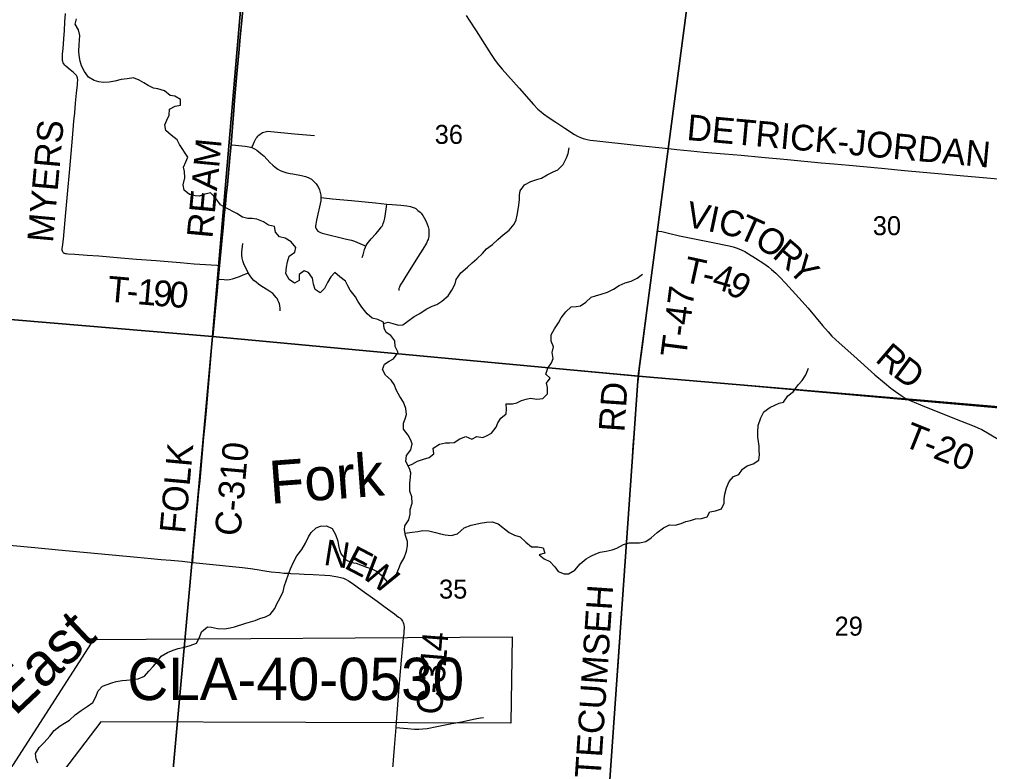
# Model space of a CAD drawing. Extents: x 0 to 1134, y 0 to 440.
# Drawn here: x 363.6 to 427.8, y 252.5 to 301.5 of the extents above; entities that cross this region are included whole.
import ezdxf

# ---------------------------------------------------------------- set-up
doc = ezdxf.new("R2010")
doc.units = 0
for name, color, linetype in [('GM_X_County_Road', 7, 'Continuous'), ('GM_X_County_Road_Text', 7, 'Continuous'), ('GM_X_Minor_River', 7, 'Continuous'), ('GM_X_Minor_River_Text', 7, 'Continuous'), ('GM_X_Section', 7, 'Continuous'), ('GM_X_Section_Text', 7, 'Continuous'), ('GM_X_Township', 7, 'Continuous'), ('GM_X_Township_Road', 7, 'Continuous'), ('GM_X_Township_Road_Text', 7, 'Continuous'), ('GM_X_Unincorporated', 7, 'Continuous'), ('SH_Text', 7, 'Continuous')]:
    doc.layers.add(name, color=color, linetype=linetype)

msp = doc.modelspace()

# ---------------------------------------------------------------- linework, layer by layer
at = {"layer": 'GM_X_County_Road'}
for points in [[(377.656, 293.203), (377.748, 294.36), (377.835, 295.474), (377.89, 296.123), (378.043, 297.887), (378.167, 299.278), (378.26, 300.299), (378.36, 301.413), (378.469, 302.619), (378.568, 303.733), (378.631, 304.475), (378.722, 305.496), (378.796, 306.331), (378.866, 307.167), (378.963, 308.187), (379.042, 309.021), (379.106, 309.67), (379.185, 310.598), (379.201, 310.758)], [(393.199, 301.754), (393.409, 301.448), (393.858, 300.74), (394.86, 299.168), (395.122, 298.781), (395.348, 298.483), (395.587, 298.196), (396.7, 296.94), (397.661, 295.866), (397.95, 295.567), (398.166, 295.372), (398.311, 295.254), (398.691, 294.983), (399.126, 294.698), (399.725, 294.299), (400.359, 293.89), (400.559, 293.778), (400.755, 293.69), (400.947, 293.618), (401.204, 293.557), (401.409, 293.517), (401.845, 293.459), (404.441, 293.182), (406.575, 292.952)], [(377.072, 287.079), (377.134, 287.694), (377.21, 288.526), (377.282, 289.267), (377.337, 289.823), (377.411, 290.564), (377.586, 292.321), (377.623, 292.783), (377.656, 293.203)], [(406.575, 292.952), (407.128, 292.893), (408.056, 292.804), (408.89, 292.724), (410.284, 292.606), (411.397, 292.511), (412.736, 292.379), (414.46, 292.227), (416.686, 292.018), (417.522, 291.947), (418.542, 291.853), (420.676, 291.65), (422.19, 291.51), (424.667, 291.287), (425.874, 291.177), (427.638, 291.021), (429.308, 290.872), (430.33, 290.787), (432, 290.631), (434.042, 290.447), (435.244, 290.336), (436.24, 290.246)], [(376.893, 285.198), (377.023, 286.581), (377.072, 287.079)], [(376.811, 284.307), (376.848, 284.726), (376.893, 285.198)], [(376.448, 280.503), (376.653, 282.628), (376.741, 283.52), (376.811, 284.307)], [(375.112, 265.584), (375.144, 266.058), (375.336, 268.189), (375.528, 270.228), (375.595, 270.97), (375.688, 271.989), (375.855, 273.844), (375.93, 274.678), (376.016, 275.605), (376.154, 277.181), (376.407, 280.056), (376.448, 280.503)], [(349.613, 267.99), (350.203, 267.933), (351.131, 267.845), (352.616, 267.712), (353.822, 267.601), (354.473, 267.548), (355.029, 267.505), (356.974, 267.342), (357.437, 267.3), (357.992, 267.241), (358.825, 267.144), (359.845, 267.04), (360.864, 266.934), (361.605, 266.857), (362.997, 266.723), (364.667, 266.562), (366.244, 266.414), (371.44, 265.931), (372.368, 265.844), (373.017, 265.783), (373.666, 265.723), (374.417, 265.654), (375.112, 265.584)], [(375.112, 265.584), (376.67, 265.424), (377.745, 265.319), (378.409, 265.244), (378.937, 265.169), (379.372, 265.101), (379.881, 265.014), (380.3, 264.958), (380.847, 264.902), (381.133, 264.878), (381.422, 264.859), (381.613, 264.85), (382.159, 264.825), (382.49, 264.809), (383.071, 264.781), (383.862, 264.732), (384.195, 264.704), (384.44, 264.675), (384.717, 264.632), (384.901, 264.589), (385.08, 264.531), (385.253, 264.455), (385.418, 264.364), (385.653, 264.209), (386.33, 263.72), (386.63, 263.502), (386.858, 263.339), (387.31, 263.007), (387.662, 262.75), (387.99, 262.512), (388.46, 262.169), (388.733, 261.968), (388.812, 261.907), (388.895, 261.827), (388.945, 261.759), (388.993, 261.688), (389.032, 261.614), (389.06, 261.534), (389.078, 261.439), (389.088, 261.333), (389.09, 261.214), (389.079, 261.049), (389.067, 260.883), (389.041, 260.586), (388.844, 258.357), (388.749, 257.337), (388.565, 255.016), (388.54, 254.662)], [(388.54, 254.662), (388.432, 253.348), (388.25, 251.119), (388.228, 250.748), (388.223, 250.621), (388.229, 250.471), (388.245, 250.287), (388.277, 250.107), (388.302, 250.019), (388.333, 249.934), (388.37, 249.851), (388.414, 249.772), (388.464, 249.696), (388.52, 249.623), (388.566, 249.571)]]:
    msp.add_lwpolyline(points, dxfattribs=at)
at = {"layer": 'GM_X_Minor_River'}
for points in [[(381.224, 287.015), (380.861, 287.122), (380.591, 287.433), (380.527, 287.787), (380.13, 287.883), (379.802, 288.104), (379.36, 288.291), (379.041, 288.329), (378.757, 288.333), (378.404, 288.417), (378.031, 288.661), (377.261, 289.057), (376.956, 289.22), (376.665, 289.623), (376.282, 290.015), (375.859, 289.906), (375.55, 289.796), (375.265, 289.822), (374.891, 289.918), (374.552, 290.195), (374.477, 290.561), (374.597, 291.015), (374.579, 291.437), (374.503, 291.723), (374.655, 292.075), (374.796, 292.392), (374.237, 293.219), (374.081, 293.529), (373.697, 293.841), (373.337, 294.142), (373.273, 294.519), (373.402, 294.825), (373.554, 295.165), (373.582, 295.552), (373.949, 295.753), (374.303, 295.828), (374.297, 296.193), (373.923, 296.425), (373.616, 296.452), (373.244, 296.764), (372.801, 296.895), (372.517, 296.955), (372.166, 297.119), (371.872, 297.293), (371.566, 297.468), (371.192, 297.632), (370.77, 297.557), (370.37, 297.517), (369.97, 297.419), (369.582, 297.344), (369.183, 297.326), (368.898, 297.363), (368.603, 297.458), (368.23, 297.679), (367.95, 298.047), (367.76, 298.414), (367.673, 298.723), (367.609, 299.1), (367.59, 299.385), (367.596, 299.818), (367.634, 300.125), (367.649, 300.433), (367.562, 300.81), (367.339, 301.177), (367.423, 301.529)], [(387.739, 281.378), (388.049, 281.474), (388.356, 281.38), (388.73, 281.273), (389.016, 281.303), (389.349, 281.527), (389.763, 281.853), (390.13, 282.042), (390.556, 282.334), (390.957, 282.534), (391.255, 282.645), (391.588, 282.869), (392.014, 283.206), (392.258, 283.59), (392.468, 283.998), (392.529, 284.282), (392.842, 284.723), (393.28, 285.117), (393.591, 285.398), (393.902, 285.668), (394.271, 286.017), (394.549, 286.31), (394.94, 286.602), (395.286, 286.929), (395.654, 287.255), (396.045, 287.547), (396.381, 287.941), (396.498, 288.236), (396.582, 288.555), (396.632, 288.919), (396.693, 289.203), (396.72, 289.579), (396.724, 289.864), (396.773, 290.159), (397.063, 290.543), (397.476, 290.767), (397.865, 290.899), (398.185, 290.998), (398.564, 291.221), (398.954, 291.41), (399.252, 291.543), (399.621, 291.892), (399.843, 292.334), (399.938, 292.629), (400.022, 292.993)], [(382.777, 267.264), (382.94, 267.558), (383.274, 267.862), (383.572, 267.984), (383.971, 267.99), (384.333, 267.826), (384.556, 267.425), (384.722, 266.99), (384.764, 266.704), (384.828, 266.407), (384.927, 266.12), (385.23, 265.741), (385.615, 265.565), (385.923, 265.539), (386.32, 265.374), (386.615, 265.268), (386.91, 265.173), (387.272, 265.009), (387.644, 264.697), (387.947, 264.317), (388.325, 264.427), (388.58, 264.766), (388.744, 265.174), (388.851, 265.469), (389.095, 265.888), (389.26, 266.331), (389.322, 266.672), (389.325, 266.969), (389.193, 267.358), (389.118, 267.724), (389.145, 268.009), (389.4, 268.405), (389.485, 268.78), (389.489, 269.076), (389.62, 269.508), (389.613, 269.907), (389.47, 270.296), (389.477, 270.821), (389.516, 271.219), (389.542, 271.504), (389.443, 271.802), (389.21, 272.249), (389.249, 272.659), (389.55, 273.032), (389.623, 273.43), (389.524, 273.716), (389.357, 274.003), (389.054, 274.394), (389.059, 274.782), (389.165, 275.077), (389.26, 275.372), (389.219, 275.749), (389.065, 276.173), (388.819, 276.552), (388.597, 276.954), (388.442, 277.343), (388.24, 277.642), (387.857, 277.954), (387.657, 278.344), (387.809, 278.684), (388.097, 278.898), (388.384, 279.054), (388.708, 279.46), (388.507, 279.85), (388.478, 280.227), (388.209, 280.583), (387.915, 280.781), (387.771, 281.067), (387.73, 281.467), (387.368, 281.653), (386.981, 281.726), (386.655, 282.027), (386.307, 282.453), (386.027, 282.855), (385.882, 283.142), (385.534, 283.579), (385.379, 283.877), (385.223, 284.187), (384.839, 284.476), (384.512, 284.765), (384.247, 284.472), (384.025, 284.098), (383.826, 283.69), (383.538, 283.409), (383.222, 283.64), (383.112, 283.984), (383.037, 284.384), (382.78, 284.751), (382.485, 284.857), (382.163, 284.622), (382.147, 284.235), (381.837, 284.056), (381.487, 284.299), (381.264, 284.69), (381.326, 285.111), (381.376, 285.452), (381.495, 285.838), (381.862, 286.096), (381.935, 286.403), (381.62, 286.783), (381.224, 287.015)], [(389.356, 271.968), (389.618, 272.085), (389.985, 272.274), (390.374, 272.418), (390.763, 272.516), (391.051, 272.763), (391.01, 273.129), (391.435, 273.408), (391.823, 273.495), (392.108, 273.48), (392.405, 273.5), (392.784, 273.746), (393.173, 273.901), (393.581, 273.725), (393.903, 273.904), (394.301, 273.842), (394.587, 273.975), (394.885, 274.12), (395.175, 274.527), (395.305, 274.822), (395.491, 275.128), (395.847, 275.397), (395.874, 275.705), (395.856, 276.07), (396.266, 276.076), (396.552, 276.141), (396.85, 276.297), (397.17, 276.373), (397.456, 276.45), (397.877, 276.376), (398.265, 276.417), (398.576, 276.733), (398.582, 277.143), (398.517, 277.429), (398.76, 277.768), (398.467, 278.034), (398.609, 278.431), (398.853, 278.782), (398.959, 279.077), (398.895, 279.454), (398.969, 279.829), (398.825, 280.219), (398.831, 280.64), (399.041, 281.025), (399.296, 281.421), (399.483, 281.761), (399.796, 282.156), (400.153, 282.494), (400.472, 282.513), (400.758, 282.555), (401.114, 282.802), (401.46, 283.117), (401.746, 283.205), (402.124, 283.326), (402.547, 283.458), (402.937, 283.658), (403.316, 283.905), (403.717, 284.06), (404.117, 284.192), (404.507, 284.381), (404.864, 284.639)], [(389.163, 267.505), (389.618, 267.581), (389.995, 267.634), (390.337, 267.687), (390.724, 267.67), (391.179, 267.551), (391.497, 267.479), (391.815, 267.395), (392.202, 267.357), (392.625, 267.477), (393.074, 267.871), (393.533, 268.048), (393.841, 268.101), (394.127, 268.166), (394.538, 268.241), (394.914, 268.259), (395.311, 268.141), (396.045, 267.562), (396.407, 267.386), (396.77, 267.268), (397.142, 266.922), (397.526, 266.621), (397.936, 266.616), (398.3, 266.543), (398.398, 266.2), (398.032, 266.079), (398.348, 265.813), (398.744, 265.637), (399.059, 265.28), (399.294, 264.98), (399.68, 264.828), (399.976, 264.824), (400.378, 265.059), (400.748, 265.488), (401.139, 265.814), (401.45, 266.004), (401.77, 266.148), (402.068, 266.259), (402.468, 266.323), (402.856, 266.409), (403.165, 266.52), (403.602, 266.765), (403.979, 266.875), (404.264, 266.883), (404.663, 266.867), (405.074, 266.965), (405.43, 267.211), (405.834, 267.548), (406.248, 267.874), (406.638, 268.064), (407.013, 268.036), (407.414, 268.157), (407.734, 268.279), (408.032, 268.344), (408.363, 268.454), (408.763, 268.495), (409.129, 268.593), (409.315, 268.933), (409.692, 268.985), (410.081, 269.129), (410.268, 269.492), (410.261, 269.788), (410.299, 270.084), (410.429, 270.516), (410.594, 270.936), (410.883, 271.252), (411.227, 271.385), (411.482, 271.758), (411.781, 271.971), (412.193, 272.103), (412.561, 272.338), (412.599, 272.703), (412.58, 272.988), (412.572, 273.273), (412.542, 273.57), (412.489, 273.856), (412.482, 274.209), (412.521, 274.642), (412.687, 275.153), (412.897, 275.538), (413.277, 275.819), (413.609, 275.986), (413.896, 276.108), (414.182, 276.185), (414.483, 276.603), (414.852, 276.884), (415.153, 277.325), (415.419, 277.618), (415.663, 277.992), (415.84, 278.434)], [(364.868, 252.292), (364.757, 252.589), (364.705, 252.944), (364.949, 253.34), (365.295, 253.666), (365.665, 254.084), (365.943, 254.456), (366.335, 254.782), (366.633, 254.938), (366.955, 255.151), (367.335, 255.5), (367.726, 255.792), (368.129, 256.06), (368.496, 256.307), (368.706, 256.692), (368.859, 257.078), (369.137, 257.405), (369.446, 257.504), (369.755, 257.626), (370.041, 257.702), (370.441, 257.766), (370.737, 257.796), (371.148, 257.826), (371.502, 257.89), (371.915, 258.067), (372.215, 258.383), (372.504, 258.699), (372.735, 258.992), (373.036, 259.376), (373.438, 259.622), (373.828, 259.777), (374.159, 259.876), (374.56, 259.985), (374.949, 260.094), (375.361, 260.249), (375.57, 260.611), (375.7, 260.986), (376.081, 261.312), (376.365, 261.297), (376.763, 261.201), (377.207, 261.196), (377.596, 261.26), (377.881, 261.325), (378.636, 261.567), (378.945, 261.654), (379.243, 261.73), (379.552, 261.864), (379.929, 261.984), (380.228, 262.14), (380.54, 262.536), (380.681, 262.842), (380.902, 263.238), (381.09, 263.647), (381.186, 264.044), (381.293, 264.351), (381.458, 264.794), (381.588, 265.157), (381.787, 265.599), (381.997, 266.019), (382.333, 266.436), (382.578, 266.855), (382.777, 267.264)]]:
    msp.add_lwpolyline(points, dxfattribs=at)
at = {"layer": 'GM_X_Section'}
for points in [[(349.223, 313.27), (378.992, 310.617), (376.424, 280.529), (346.29, 283.052)], [(378.992, 310.617), (408.53, 307.786), (404.58, 277.901), (376.424, 280.529)], [(408.53, 307.786), (437.721, 305.198), (434.906, 275.318), (404.58, 277.901)], [(346.29, 283.052), (376.424, 280.529), (373.702, 250.716), (343.437, 253.571)], [(376.424, 280.529), (404.58, 277.901), (402.471, 248.078), (373.702, 250.716)], [(404.58, 277.901), (434.906, 275.318), (432.306, 245.32), (402.471, 248.078)]]:
    msp.add_lwpolyline(points, close=True, dxfattribs=at)
at = {"layer": 'GM_X_Township'}
msp.add_lwpolyline([(300.527, 287.945), (340.569, 283.778), (346.334, 283.109), (376.441, 280.519), (404.61, 277.916), (422.488, 276.334), (434.927, 275.233)], dxfattribs=at)
at = {"layer": 'GM_X_Township_Road'}
for points in [[(376.893, 285.198), (376.703, 285.211), (375.201, 285.314), (374.273, 285.394), (372.696, 285.522), (371.398, 285.625), (370.362, 285.71), (368.897, 285.825), (368.131, 285.884), (367.312, 285.948), (366.848, 285.974), (366.753, 285.98), (366.705, 285.988), (366.657, 286.002), (366.616, 286.021), (366.572, 286.052), (366.541, 286.085), (366.512, 286.13), (366.494, 286.174), (366.484, 286.225), (366.48, 286.272), (366.48, 286.337), (366.491, 286.446), (366.564, 286.969), (366.729, 288.73), (366.83, 289.936), (366.977, 291.606), (367.167, 293.646), (367.26, 294.759), (367.306, 295.316), (367.364, 295.964), (367.429, 296.612), (367.49, 297.167), (367.501, 297.314), (367.504, 297.444), (367.507, 297.515), (367.5, 297.57), (367.488, 297.632), (367.464, 297.699), (367.416, 297.781), (367.369, 297.84), (367.313, 297.899), (367.222, 297.984), (367.013, 298.169), (366.729, 298.412), (366.661, 298.478), (366.598, 298.55), (366.548, 298.63), (366.529, 298.673), (366.515, 298.719), (366.505, 298.767), (366.499, 298.813), (366.497, 298.908), (366.51, 299.189), (366.535, 299.56), (366.582, 300.209), (366.622, 300.766), (366.658, 301.324), (366.705, 301.881)], [(379.031, 293.011), (379.05, 293.063), (379.124, 293.272), (379.189, 293.424), (379.261, 293.554), (379.312, 293.632), (379.368, 293.707), (379.429, 293.777), (379.496, 293.842), (379.567, 293.903), (379.644, 293.957), (379.724, 294.003), (379.81, 294.04), (379.899, 294.068), (379.99, 294.087), (380.083, 294.094), (380.27, 294.086), (381.85, 293.934), (383.168, 293.82)], [(377.656, 293.203), (377.719, 293.198), (377.937, 293.181), (378.585, 293.111), (378.841, 293.068), (379.031, 293.011)], [(379.031, 293.011), (379.193, 292.942), (379.354, 292.842), (379.483, 292.745), (379.628, 292.633), (379.832, 292.444), (380.22, 292.04), (380.423, 291.844), (380.568, 291.724), (380.733, 291.598), (380.898, 291.507), (381.08, 291.437), (381.333, 291.355), (381.56, 291.306), (381.737, 291.276), (382.311, 291.163), (382.563, 291.107), (382.741, 291.046), (382.885, 290.981), (382.976, 290.924), (383.046, 290.868), (383.156, 290.753), (383.219, 290.687), (383.277, 290.617), (383.33, 290.543), (383.422, 290.384), (383.494, 290.215), (383.548, 290.04), (383.581, 289.86), (383.59, 289.769), (383.591, 289.725)], [(405.863, 287.511), (405.99, 288.498), (406.266, 290.617), (406.462, 292.091), (406.533, 292.636), (406.566, 292.887), (406.575, 292.952)], [(383.591, 289.725), (383.592, 289.677), (383.588, 289.586), (383.577, 289.495), (383.308, 288.219), (383.253, 287.943), (383.242, 287.847), (383.244, 287.747), (383.268, 287.652), (383.32, 287.567), (383.39, 287.494), (383.472, 287.435), (383.572, 287.393), (383.676, 287.363), (385.289, 286.968), (385.616, 286.889), (385.824, 286.819), (386.17, 286.676), (386.421, 286.557), (386.563, 286.49)], [(383.591, 289.725), (383.775, 289.702), (384.329, 289.635), (385.625, 289.508), (387.199, 289.359), (387.948, 289.284)], [(386.563, 286.49), (386.585, 286.541), (386.659, 286.658), (386.732, 286.766), (386.906, 286.98), (387.218, 287.322), (387.471, 287.596), (387.585, 287.746), (387.636, 287.826), (387.681, 287.909), (387.72, 287.995), (387.782, 288.173), (387.827, 288.355), (387.874, 288.631), (387.927, 289.092), (387.948, 289.284)], [(387.948, 289.284), (388.31, 289.248), (388.881, 289.202), (389.268, 289.159), (389.512, 289.111), (389.69, 289.063), (389.781, 289.028), (389.864, 288.981), (389.947, 288.924), (390.012, 288.866), (390.152, 288.744), (390.217, 288.677), (390.277, 288.606), (390.332, 288.531), (390.428, 288.372), (390.551, 288.122), (390.624, 287.95), (390.683, 287.774), (390.722, 287.592), (390.74, 287.407), (390.74, 287.314), (390.735, 287.221), (390.724, 287.129), (390.706, 287.038), (390.681, 286.948), (390.649, 286.861), (390.571, 286.692), (390.336, 286.291), (389.991, 285.739), (389.143, 284.404), (389.003, 284.18), (388.838, 283.91), (388.781, 283.78), (388.751, 283.688), (388.739, 283.569)], [(404.617, 277.9), (404.671, 278.391), (404.854, 279.839), (405.173, 282.234), (405.292, 283.155), (405.364, 283.708), (405.458, 284.445), (405.541, 285.089), (405.655, 285.918), (405.776, 286.84), (405.863, 287.511)], [(405.863, 287.511), (405.923, 287.499), (406.133, 287.458), (406.586, 287.352), (407.312, 287.188), (408.313, 286.977), (409.408, 286.76), (410.592, 286.519), (410.862, 286.455), (411.124, 286.37), (411.379, 286.262), (411.627, 286.137), (411.868, 285.999), (412.341, 285.704), (412.884, 285.346), (413.187, 285.134), (413.404, 284.961), (413.68, 284.714), (413.945, 284.455), (414.325, 284.048), (415.195, 283.079), (415.813, 282.385), (416.768, 281.244), (417.136, 280.823), (417.394, 280.554), (417.871, 280.109), (418.842, 279.241), (420.222, 277.994), (420.86, 277.45), (421.297, 277.102), (421.597, 276.881), (422.047, 276.571), (422.24, 276.448), (422.354, 276.387), (422.495, 276.318)], [(378.791, 284.729), (378.729, 284.843), (378.613, 285.083), (378.494, 285.337), (378.426, 285.528), (378.383, 285.705), (378.364, 285.901), (378.36, 286.093), (378.374, 286.293), (378.418, 286.666)], [(386.319, 285.747), (386.381, 285.932), (386.481, 286.271), (386.538, 286.432), (386.563, 286.49)], [(376.811, 284.307), (376.881, 284.303), (377.197, 284.286), (377.345, 284.279), (377.537, 284.293), (377.748, 284.339), (377.943, 284.399), (378.202, 284.494), (378.441, 284.59), (378.695, 284.69), (378.791, 284.729)], [(380.901, 282.221), (380.897, 282.374), (380.876, 282.561), (380.844, 282.676), (380.776, 282.847), (380.734, 282.929), (380.69, 283.025), (380.637, 283.102), (380.546, 283.222), (380.412, 283.355), (380.274, 283.461), (380.089, 283.579), (379.695, 283.83), (379.463, 283.99), (379.314, 284.105), (379.154, 284.236), (379.02, 284.384), (378.91, 284.533), (378.82, 284.676), (378.791, 284.729)], [(402.659, 250.258), (402.867, 253.329), (402.943, 254.445), (403.062, 256.12), (403.164, 257.515), (403.269, 258.995), (403.313, 259.655), (403.376, 260.583), (403.406, 261.048), (403.44, 261.606), (403.514, 262.723), (403.598, 263.932), (403.701, 265.328), (403.835, 267.188), (403.883, 267.839), (403.96, 268.955), (404.052, 270.257), (404.119, 271.28), (404.18, 272.211), (404.256, 273.327), (404.325, 274.351), (404.377, 275.095), (404.456, 276.211), (404.534, 277.14), (404.617, 277.9)], [(422.495, 276.318), (422.61, 276.264), (422.822, 276.171), (423.242, 275.994), (425.059, 275.267), (426.016, 274.899), (426.798, 274.599), (427.053, 274.488), (427.301, 274.364), (427.788, 274.092), (428.504, 273.656)], [(388.54, 254.662), (389.327, 254.587), (389.788, 254.558), (390.066, 254.554), (390.343, 254.57), (390.618, 254.604), (391.254, 254.726), (392.252, 254.921), (392.887, 255.042), (393.793, 255.231), (394.157, 255.295), (394.34, 255.319)]]:
    msp.add_lwpolyline(points, dxfattribs=at)
at = {"layer": 'GM_X_Unincorporated'}
for points in [[(346.334, 283.109), (376.441, 280.519), (376.646, 282.644), (376.734, 283.536), (376.804, 284.323), (376.841, 284.742), (376.886, 285.214), (377.016, 286.597), (377.127, 287.71), (377.203, 288.542), (377.275, 289.283), (377.33, 289.839), (377.405, 290.58), (377.579, 292.337), (377.616, 292.799), (377.649, 293.219), (377.741, 294.376), (377.828, 295.49), (377.883, 296.139), (378.036, 297.903), (378.16, 299.294), (378.253, 300.315), (378.353, 301.429), (378.462, 302.635)], [(378.462, 302.635), (378.353, 301.429), (378.253, 300.315), (378.16, 299.294), (378.036, 297.903), (377.883, 296.139), (377.828, 295.49), (377.741, 294.376), (377.649, 293.219), (377.616, 292.799), (377.579, 292.337), (377.405, 290.58), (377.33, 289.839), (377.275, 289.283), (377.203, 288.542), (377.127, 287.71), (377.016, 286.597), (376.886, 285.214), (376.841, 284.742), (376.804, 284.323), (376.734, 283.536), (376.646, 282.644), (376.441, 280.519), (404.61, 277.916), (422.488, 276.334), (434.927, 275.233)]]:
    msp.add_lwpolyline(points, dxfattribs=at)
at = {"layer": 'SH_Text'}
msp.add_lwpolyline([(343.646, 221.728), (368.576, 260.481), (396.248, 260.648), (396.155, 254.95), (369.025, 255.034)], close=True, dxfattribs=at)

# ---------------------------------------------------------------- texts
at = {"layer": 'GM_X_County_Road_Text'}
for s, height, rotation, p in [('DETRICK-JORDAN', 1.70455, 354.76244, (407.745, 293.527)), ('REAM', 1.7045, 84.58912, (376.414, 286.971)), ('FOLK', 1.7045, 84.78199, (374.614, 267.445)), ('C-310', 1.7045, 84.78233, (378.257, 267.274)), ('N', 1.705, 351.07908, (383.718, 265.43)), ('E', 1.705, 332.34625, (385.061, 265.243)), ('W', 1.705, 324.18316, (386.136, 264.685)), ('4', 1.705, 85.56175, (391.933, 259.658)), ('1', 1.705, 85.30915, (391.846, 258.603)), ('3', 1.705, 85.21694, (391.759, 257.554)), ('-', 1.705, 85.19357, (391.7, 256.856)), ('C', 1.705, 85.19357, (391.583, 255.461))]:
    msp.add_text(s, height=height, rotation=rotation, dxfattribs=at).set_placement(p)
at = {"layer": 'GM_X_Minor_River_Text'}
for s, height, rotation, p in [('Fork', 2.8409, 4.28297, (380.269, 269.448)), ('East', 2.8419, 43.42796, (363.355, 255.357))]:
    msp.add_text(s, height=height, rotation=rotation, dxfattribs=at).set_placement(p)
at = {"layer": 'GM_X_Section_Text'}
for s, p in [('36', (391.119, 293.261)), ('30', (420.094, 287.223)), ('35', (391.407, 263.186)), ('29', (417.569, 260.736))]:
    msp.add_text(s, height=1.2557, rotation=0.00001, dxfattribs=at).set_placement(p)
at = {"layer": 'GM_X_Township_Road_Text'}
for s, height, rotation, p in [('MYERS', 1.7045, 84.85669, (365.864, 286.695)), ('V', 1.705, 348.19783, (407.644, 287.816)), ('I', 1.705, 348.16803, (409.112, 287.509)), ('C', 1.705, 347.2011, (409.789, 287.367)), ('T', 1.705, 335.89653, (411.07, 287.085)), ('O', 1.705, 326.54029, (412.17, 286.6)), ('R', 1.705, 319.57778, (413.378, 285.805)), ('T', 1.705, 347.67805, (407.476, 284.168)), ('Y', 1.705, 313.10638, (414.407, 284.933)), ('4', 1.705, 343.5435, (409.374, 283.754)), ('T', 1.705, 355.031, (369.425, 282.837)), ('1', 1.705, 355.06433, (371.394, 282.666)), ('-', 1.705, 347.60158, (408.721, 283.896)), ('9', 1.705, 327.85727, (410.269, 283.507)), ('9', 1.705, 355.19294, (372.444, 282.575)), ('0', 1.705, 355.79117, (373.51, 282.485)), ('T-47', 1.7045, 82.66007, (407.741, 279.082)), ('-', 1.705, 355.03939, (370.696, 282.726)), ('R', 1.705, 319.50878, (420.189, 278.924)), ('D', 1.705, 323.59531, (421.356, 277.934)), ('RD', 1.7045, 86.05084, (403.662, 274.17)), ('T-20', 1.7045, 338.2081, (422.015, 273.309)), ('TECUMSEH', 1.7045, 86.21098, (402.086, 251.273))]:
    msp.add_text(s, height=height, rotation=rotation, dxfattribs=at).set_placement(p)
at = {"layer": 'SH_Text'}
msp.add_text('CLA-40-0530', height=2.8, dxfattribs=at).set_placement((370.791, 256.475))

doc.saveas('drawing.dxf')
